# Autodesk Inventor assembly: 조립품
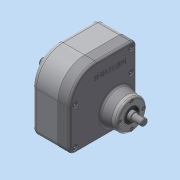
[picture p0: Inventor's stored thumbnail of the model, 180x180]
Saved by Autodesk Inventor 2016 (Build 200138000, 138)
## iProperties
Created: 2015-11
Part Number: 조립품
Document SubType Name: Assembly
Designer: KET-DEVEL
Author: KET-DEVEL
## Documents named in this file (13)
- C:\Users\KET-DEVEL\Desktop\Inventor2급-김남원\Inventor2급-김남원\조립품.iam
- C:\Users\KET-DEVEL\Desktop\Inventor2급-김남원\Inventor2급-김남원\본체-김남원.ipt
- C:\Users\KET-DEVEL\Desktop\Inventor2급-김남원\Inventor2급-김남원\공용부품_20151104_2\M3 x 0.5.ipt
- C:\Users\KET-DEVEL\Desktop\Inventor2급-김남원\Inventor2급-김남원\공용부품_20151104_2\M4 x 0.7.ipt
- C:\Users\KET-DEVEL\Desktop\Inventor2급-김남원\Inventor2급-김남원\공용부품_20151104_2\로드 축.ipt
- C:\Users\KET-DEVEL\Desktop\Inventor2급-김남원\Inventor2급-김남원\공용부품_20151104_2\로드.ipt
- C:\Users\KET-DEVEL\Desktop\Inventor2급-김남원\Inventor2급-김남원\공용부품_20151104_2\베어링 6001.ipt
- C:\Users\KET-DEVEL\Desktop\Inventor2급-김남원\Inventor2급-김남원\공용부품_20151104_2\베어링 6002.ipt
- C:\Users\KET-DEVEL\Desktop\Inventor2급-김남원\Inventor2급-김남원\공용부품_20151104_2\앞커버.ipt
- C:\Users\KET-DEVEL\Desktop\Inventor2급-김남원\Inventor2급-김남원\공용부품_20151104_2\오일실 12 x 22.ipt
- C:\Users\KET-DEVEL\Desktop\Inventor2급-김남원\Inventor2급-김남원\공용부품_20151104_2\오일실 15 x 25.ipt
- C:\Users\KET-DEVEL\Desktop\Inventor2급-김남원\Inventor2급-김남원\공용부품_20151104_2\축 커버.ipt
- C:\Users\KET-DEVEL\Desktop\Inventor2급-김남원\Inventor2급-김남원\공용부품_20151104_2\편심 축.ipt
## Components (9 placed, 2 different names)
1. M4 x 0.7:1
2. M4 x 0.7:2
3. M4 x 0.7:3
4. M4 x 0.7:4
5. M4 x 0.7:5
6. M3 x 0.5:1
7. M3 x 0.5:2
8. M3 x 0.5:3
9. M3 x 0.5:4
